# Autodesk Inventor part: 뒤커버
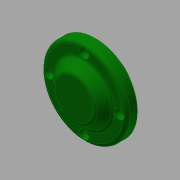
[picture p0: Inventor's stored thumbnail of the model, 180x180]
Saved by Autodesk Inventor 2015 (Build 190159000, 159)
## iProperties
Created: 2017-08
Part Number: 뒤커버
Material: 알루미늄 6061
Document SubType Name: Modeling
Designer: mduedu
Density: 1 g/cm^3
Appearance: 진녹색
Author: mduedu
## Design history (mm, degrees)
sketch "스케치1"
  geometry: C1 r 35 at (0, 0); 1 further point
  constraints: 1 centre point, 1 coincident
  dimensions: "d0" = 70 diameter of C1
extrude "돌출1" new body sketch "스케치1" distance "d1" = 10; taper "d2" = 0 deg
sketch "스케치2"
  geometry: C1 r 24 at (0, 0); 1 further point
  constraints: 1 centre point, 1 coincident
  dimensions: "d3" = 48 diameter of C1
node "작업 평면1"
sketch "스케치3"
  geometry: C1 r 17 at (0, 0); 1 further point
  constraints: 1 centre point, 1 coincident
  dimensions: "d5" = 34 diameter of C1
feature "로프트1" sketch "스케치3" dims "d6" = 0, "d7" = 90 deg, "d8" = 0, "d9" = 90 deg
sketch "스케치4"
  geometry: C1 r 24 at (0, 0) reference; 1 further point
extrude "돌출2" join sketch "스케치4" distance "d10" = 8; taper "d11" = 0 deg
hole "구멍1" diameter "d14" = 40; stored, may be unused: countersink angle "d18" = 90 deg, drill point angle "d20" = 0 deg; dims "d12" = 10, "d13" = 10, "d15" = 6, "d16" = 4, "d17" = 2, "d19" = 12
hole "구멍2" diameter "d23" = 34; stored, may be unused: countersink angle "d27" = 90 deg, drill point angle "d29" = 0 deg; dims "d24" = 6, "d25" = 4, "d26" = 2, "d28" = 6, "d62" = 10, "d63" = 10
chamfer "모따기1" distance "d39" = 1; stored, may be unused: second distance "d40" = 2, angle "d41" = 45 deg
fillet "모깎기1" dims "d42" = 0.3
fillet "모깎기2" dims "d43" = 3
sketch "스케치5" dims "d44" = 58
  geometry: 6 further points
  constraints: 2 vertical alignment, 1 coincident, 7 other
  dimensions: "d47" = 360 deg dimension on point (0, 0) point (0, 29) (derived)
sketch "스케치6"
  geometry: 4 further points
  constraints: 4 other
hole "구멍4" sketch "스케치6" at (0, 29), (-29, 0), (29, 0), (0, -29) diameter "d49" = 4.5; stored, may be unused: countersink angle "d53" = 90 deg, drill point angle "d55" = 0 deg; dims "d50" = 6, "d51" = 8, "d52" = 4.6, "d54" = 8
fillet "모깎기3" dims "d56" = 3
fillet "모깎기4" dims "d57" = 3
fillet "모깎기5" dims "d58" = 3
chamfer "모따기2" distance "d59" = 1; stored, may be unused: second distance "d60" = 2, angle "d61" = 45 deg
node "솔리드1"
other parameters: "d4" = 8
